// Mitsubishi GX Works2 project: MM-42MR-8MTS-F700-FX3U-C   PLC: FX3U/FX3UC

PROGRAM MAIN
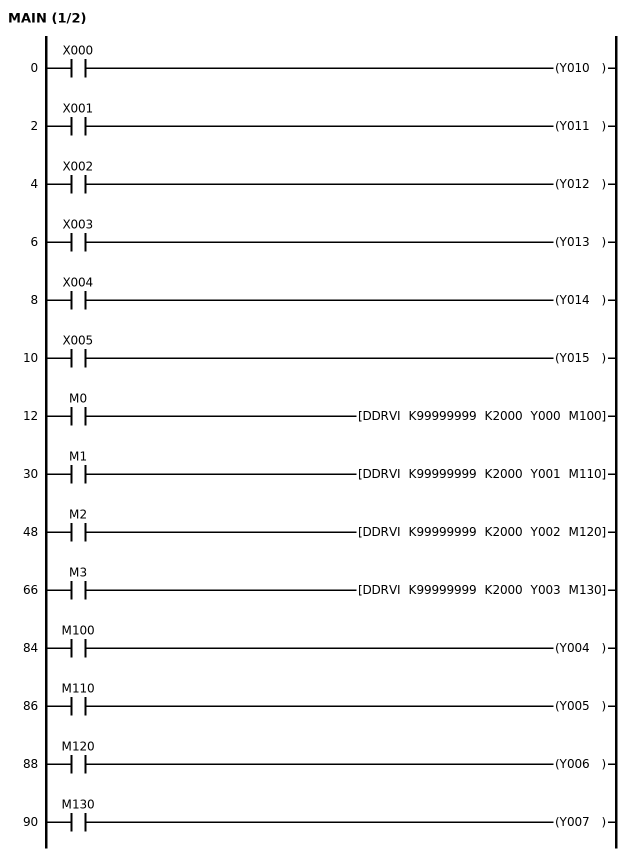
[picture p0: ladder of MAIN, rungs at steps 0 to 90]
0     LD      X000
      OUT     Y010
2     LD      X001
      OUT     Y011
4     LD      X002
      OUT     Y012
6     LD      X003
      OUT     Y013
8     LD      X004
      OUT     Y014
10    LD      X005
      OUT     Y015
12    LD      M0
      DDRVI   K99999999 K2000 Y000 M100
30    LD      M1
      DDRVI   K99999999 K2000 Y001 M110
48    LD      M2
      DDRVI   K99999999 K2000 Y002 M120
66    LD      M3
      DDRVI   K99999999 K2000 Y003 M130
84    LD      M100
      OUT     Y004
86    LD      M110
      OUT     Y005
88    LD      M120
      OUT     Y006
90    LD      M130
      OUT     Y007
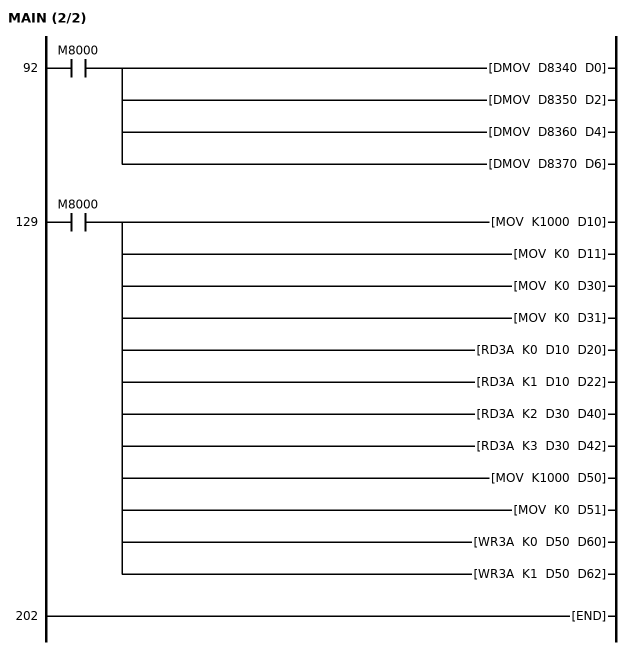
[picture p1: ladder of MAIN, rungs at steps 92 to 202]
92    LD      M8000
      DMOV    D8340 D0
      DMOV    D8350 D2
      DMOV    D8360 D4
      DMOV    D8370 D6
129   LD      M8000
      MOV     K1000 D10
      MOV     K0 D11
      MOV     K0 D30
      MOV     K0 D31
      RD3A    K0 D10 D20
      RD3A    K1 D10 D22
      RD3A    K2 D30 D40
      RD3A    K3 D30 D42
      MOV     K1000 D50
      MOV     K0 D51
      WR3A    K0 D50 D60
      WR3A    K1 D50 D62
202   END
END_PROGRAM
